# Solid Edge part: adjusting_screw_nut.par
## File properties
Title: Adjusting screw nut
Author: Abhinav Rai
Template: Normal.par
Last saved by: SOFT
Revision: 31
Application: Solid Edge
Accuracy: 0.99
Material: aluminum
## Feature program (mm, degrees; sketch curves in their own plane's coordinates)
sketch for "unnamed RevolvedProtrusion 1" plane through (0, 0, 0) normal (0, -1, 0) x-axis (1, 0, 0)
  line (25.4, 9.7462) -> (74.676, 9.7462)
  line (76.2, 8.2222) -> (74.676, 9.7462)
  line (76.2, -26.8298) -> (76.2, 8.2222)
  line (76.2, -26.8298) -> (74.676, -28.3538)
  line (74.676, -28.3538) -> (47.625, -28.3538)
  line (47.625, -28.3538) -> (47.625, -60.1038)
  line (47.625, -60.1038) -> (25.4, -60.1038)
  line (25.4, -60.1038) -> (25.4, 9.7462)
revolve "unnamed RevolvedProtrusion 1" add full turn 360 deg
sketch for "Hole_1" plane through (76.2, 0, 0) normal (1, 0, 0) x-axis (0, 1, 0)
  hole centre (0, -9.3038) bore radius 9.5123
hole "Hole_1" diameter 19.0246 finite  VBottomAngle = 118 deg
pattern "unnamed Pattern 1" of "Hole_1"
pattern "unnamed Pattern 2"
sketch for "unnamed Cutout 1" plane through (0, 0, 9.7462) normal (0, 0, 1) x-axis (1, 0, 0)
extrude "unnamed Cutout 1" cut through along -normal
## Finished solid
Body 1: solid body, 16 faces, 16 edges, 4 vertices.
  Faces by surface: cylinder 7, cone 6, plane 3
  Edges by curve: circle 12, intersection 4
Bounding box of the edges (mm): 152.400 x 152.400 x 69.850, from (-76.2, -76.2, -60.1038) to (76.2, 76.2, 9.7462).
Cylindrical faces by radius (mm): R9.5123 x4, R38.1 x1, R47.625 x1, R76.2 x1
Conical faces (half-angle, radius in mm at the cone's reference point): 45 deg R74.676 x1, 45 deg R76.2 x1, 59 deg R9.5123 x4
Planar faces by outward normal: +z 1, -z 2
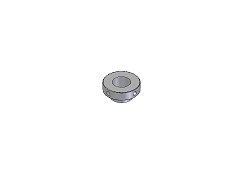
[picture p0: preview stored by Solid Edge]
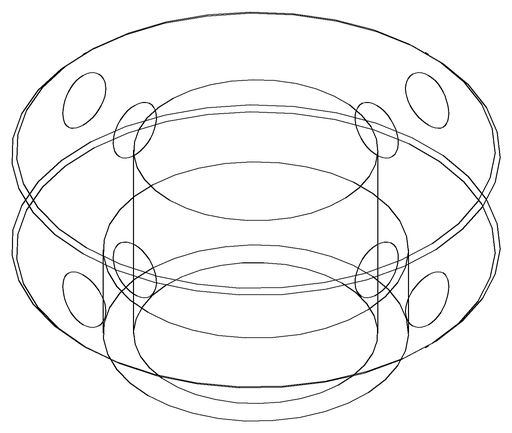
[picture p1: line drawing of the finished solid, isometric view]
